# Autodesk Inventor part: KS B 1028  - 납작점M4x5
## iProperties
IsCustomPart: 0
Created: 2009-02
Part Number: KS B 1028  - 납작점M4x5
Material: 강, 연강
Description: 6각 소켓 머리 없는 멈춤 나사
Document SubType Name: Modeling
Standard: KS B 1028
Designer: KYOUNG IL JANG
Standards Organization: KS
Language: ko-KR
Size Designation: 납작점M4x5
Categories: <MemberInstance><Categories><Category DisplayName="조임쇠" InternalName="e4da775c-781d-43d5-af7c-5136215cf5a6" Mnemonic="FSTN"><Category DisplayName="볼트" InternalN
Density: 1 g/cm^3
Author: KYOUNG IL JANG
